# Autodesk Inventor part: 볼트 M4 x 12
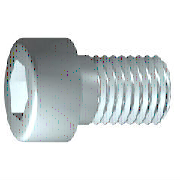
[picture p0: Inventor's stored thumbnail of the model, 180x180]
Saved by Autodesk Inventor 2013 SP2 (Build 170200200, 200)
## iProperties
IsCustomPart: 1
Created: 2012-02
Part Number: 볼트 M4 x 12
Material: 스테인리스강
Description: 6각 소켓 머리 캡 나사
Document SubType Name: Modeling
Standard: ISO 4762
Designer: mduedu
Standard Revision: Fourth edition 2004-03-01
Standards Organization: ISO
Language: ko-KR
Size Designation: M4 x 12
Categories: <MemberInstance><Categories><Category DisplayName="조임쇠" InternalName="e4da775c-781d-43d5-af7c-5136215cf5a6" Mnemonic="FSTN"><Category DisplayName="볼트" InternalN
Density: 8.08 g/cm^3
Author: mduedu
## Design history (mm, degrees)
sketch "스케치1"
  geometry: L1 (-1, 0)-(12, 0); L2 (12, 0)-(12, 2); L3 (12, 2)-(1.75, 2); L4 (1.75, 2)-(1.32, 2); L5 (1.32, 2)-(0, 2); L6 (0, 2)-(0, 3.5); L7 (0, 3.5)-(-4, 3.5); L8 (-4, 3.5)-(-4, 1.732); L9 (-4, 1.732)-(-2, 1.732); L10 (-2, 1.732)-(-1, 0); L11 (-7.2, 0)-(15.2, 0) reference; L12 (0, -0.7)-(0, 4.2) reference; L13 (1.75, 2)-(0, 2)
  constraints: 22 end point, 6 parallel, 2 collinear, 2 perpendicular, 1 horizontal, 1 point on line
  dimensions: "d1" = 10.25 distance from line of L3.end L2 (= GEL); "d2" = 0.42952 distance of L4.end L3.end (computed from GAL); "d3" = 4 distance between parallel lines of L8 L6 (= KOH); "d4" = 2 distance of L8.end L9.end (= INTI); "d5" = 60 deg angle of L10 L1; "d6" = 4 diameter of L3 L1 (= GD); "d7" = 4 diameter of L5 L1 (= BDM); "d8" = 3.4641 diameter of L9 L1 (= 1.1547 x SW); "d9" = 7 diameter of L7 L1 (= KOD); "d26" = 12 distance between parallel lines of L12 L2 (= NLG)
revolve "본체" sketch "스케치1" stored, may be unused: angle "d10" = 90 deg
sketch "스케치2"
  geometry: L1 (0, -4.9)-(0, 4.9) reference; L2 (-4.9, 0)-(4.9, 0) reference; L3 (1.732, 0)-(0.866, -1.5); L4 (0.866, -1.5)-(-0.866, -1.5); L5 (-0.866, -1.5)-(-1.732, 0); L6 (-1.732, 0)-(-0.866, 1.5); L7 (-0.866, 1.5)-(0.866, 1.5); L8 (0.866, 1.5)-(1.732, 0); 2 further points
  constraints: 12 end point, 1 coincident, 1 horizontal alignment, 1 point on line, 12 other
extrude "슬롯" join sketch "스케치2" stored distance "d11" = 10; taper "d12" = 0 deg
workplane "Work Plane1"
fillet "Fillet2" dims "d30" = 0.1 (= R)
body "Solid1"
fillet "모깎기1" dims "d17" = 0.4 (= RR)
feature "스레드" dims "d13" = 10.25 (= GEL), "d14" = 0
chamfer "모따기1" distance "d15" = 0.42941 (= -0.5 x SPD + 0.5 x GD); stored, may be unused: second distance "d16" = 0.42941 (= GUL), angle "d27" = 45 deg
other parameters: "GD" = 4 [user parameter; used in 2 equation terms], "NLG" = 12 [user parameter; used in 1 equation term], "GEL" = 10.25 [user parameter; used in 2 equation terms], "KOD" = 7 [user parameter; used in 1 equation term], "KOH" = 4 [user parameter; used in 1 equation term], "INTI" = 2 [user parameter; used in 1 equation term], "GAL" = 0.42941 (= 0.61345 x PTC) [user parameter; used in 1 equation term], "GUL" = 0.42941 (= 0.61345 x PTC) [user parameter; used in 1 equation term], "BDM" = 4 (= NND) [user parameter; used in 1 equation term], "SW" = 3 [user parameter; used in 2 equation terms], "RR" = 0.4 [user parameter; used in 1 equation term], "SPD" = 3.14117 (= NND - 1.2269 x PTC) [user parameter; used in 1 equation term], "d19" = 0, "d28" = 0, "d29" = 0, "R" = 0.1 [user parameter; used in 1 equation term], "TOA" = 30 deg [user parameter], "GD1" = 3.14117 (= THREADDIA - 1.2269 x PTC) [user parameter], "THREADDIA" = 4 [user parameter; used in 1 equation term], "FAWI" = 45 deg [user parameter], "TPU" = 14.28571 (computed from PTC) [user parameter], "PTC" = 0.7 [user parameter; used in 5 equation terms], "NND" = 4 [user parameter; used in 2 equation terms], "E0" = 3.465 (= 1.155 x SW) [user parameter]
